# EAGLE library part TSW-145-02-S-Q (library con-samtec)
THROUGH-HOLE .025" SQ POST HEADER Source: Samtec TSW.pdf
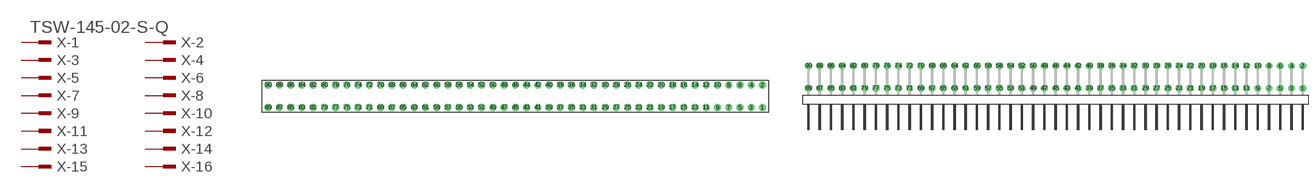
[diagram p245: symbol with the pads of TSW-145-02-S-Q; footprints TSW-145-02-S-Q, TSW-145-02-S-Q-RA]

Designator prefix X; gates -1=MPINV -2=MPIN -3=MPIN -4=MPIN -5=MPIN -6=MPIN -7=MPIN -8=MPIN -9=MPIN -10=MPIN -11=MPIN -12=MPIN -13=MPIN -14=MPIN -15=MPIN -16=MPIN -17=MPIN -18=MPIN -19=MPIN -20=MPIN -21=MPIN -22=MPIN -23=MPIN -24=MPIN -25=MPIN -26=MPIN -27=MPIN -28=MPIN -29=MPIN -30=MPIN -31=MPIN -32=MPIN -33=MPIN -34=MPIN -35=MPIN -36=MPIN -37=MPIN -38=MPIN -39=MPIN -40=MPIN -41=MPIN -42=MPIN -43=MPIN -44=MPIN -45=MPIN -46=MPIN -47=MPIN -48=MPIN -49=MPIN -50=MPIN -51=MPIN -52=MPIN -53=MPIN -54=MPIN -55=MPIN -56=MPIN -57=MPIN -58=MPIN -59=MPIN -60=MPIN -61=MPIN -62=MPIN -63=MPIN -64=MPIN -65=MPIN -66=MPIN -67=MPIN -68=MPIN -69=MPIN -70=MPIN -71=MPIN -72=MPIN -73=MPIN -74=MPIN -75=MPIN -76=MPIN -77=MPIN -78=MPIN -79=MPIN -80=MPIN -81=MPIN -82=MPIN -83=MPIN -84=MPIN -85=MPIN -86=MPIN -87=MPIN -88=MPIN -89=MPIN -90=MPIN

## TSW-145-02-S-Q (OC_FARNELL: unknown; OC_NEWARK: unknown)  [TSW-145-02-S-Q]
1  -1:1  pas
2  -2:1  pas
3  -3:1  pas
4  -4:1  pas
5  -5:1  pas
6  -6:1  pas
7  -7:1  pas
8  -8:1  pas
9  -9:1  pas
10  -10:1  pas
11  -11:1  pas
12  -12:1  pas
13  -13:1  pas
14  -14:1  pas
15  -15:1  pas
16  -16:1  pas
17  -17:1  pas
18  -18:1  pas
19  -19:1  pas
20  -20:1  pas
21  -21:1  pas
22  -22:1  pas
23  -23:1  pas
24  -24:1  pas
25  -25:1  pas
26  -26:1  pas
27  -27:1  pas
28  -28:1  pas
29  -29:1  pas
30  -30:1  pas
31  -31:1  pas
32  -32:1  pas
33  -33:1  pas
34  -34:1  pas
35  -35:1  pas
36  -36:1  pas
37  -37:1  pas
38  -38:1  pas
39  -39:1  pas
40  -40:1  pas
41  -41:1  pas
42  -42:1  pas
43  -43:1  pas
44  -44:1  pas
45  -45:1  pas
46  -46:1  pas
47  -47:1  pas
48  -48:1  pas
49  -49:1  pas
50  -50:1  pas
51  -51:1  pas
52  -52:1  pas
53  -53:1  pas
54  -54:1  pas
55  -55:1  pas
56  -56:1  pas
57  -57:1  pas
58  -58:1  pas
59  -59:1  pas
60  -60:1  pas
61  -61:1  pas
62  -62:1  pas
63  -63:1  pas
64  -64:1  pas
65  -65:1  pas
66  -66:1  pas
67  -67:1  pas
68  -68:1  pas
69  -69:1  pas
70  -70:1  pas
71  -71:1  pas
72  -72:1  pas
73  -73:1  pas
74  -74:1  pas
75  -75:1  pas
76  -76:1  pas
77  -77:1  pas
78  -78:1  pas
79  -79:1  pas
80  -80:1  pas
81  -81:1  pas
82  -82:1  pas
83  -83:1  pas
84  -84:1  pas
85  -85:1  pas
86  -86:1  pas
87  -87:1  pas
88  -88:1  pas
89  -89:1  pas
90  -90:1  pas

## TSW-145-02-S-Q-RA (OC_FARNELL: unknown; OC_NEWARK: unknown)  [TSW-145-02-S-Q-RA]
Pads as for TSW-145-02-S-Q

## Footprint TSW-145-02-S-Q (pad centres in mm)
THROUGH-HOLE .025" SQ POST HEADER Source: Samtec TSW.pdf
drill 1 pad 1.5 octagon: 1 55.88,-2.54; 2 55.88,2.54; 3 53.34,-2.54; 4 53.34,2.54; 5 50.8,-2.54; 6 50.8,2.54; 7 48.26,-2.54; 8 48.26,2.54; 9 45.72,-2.54; 10 45.72,2.54; 11 43.18,-2.54; 12 43.18,2.54; 13 40.64,-2.54; 14 40.64,2.54; 15 38.1,-2.54; 16 38.1,2.54; 17 35.56,-2.54; 18 35.56,2.54; 19 33.02,-2.54; 20 33.02,2.54; 21 30.48,-2.54; 22 30.48,2.54; 23 27.94,-2.54; 24 27.94,2.54; 25 25.4,-2.54; 26 25.4,2.54; 27 22.86,-2.54; 28 22.86,2.54; 29 20.32,-2.54; 30 20.32,2.54; 31 17.78,-2.54; 32 17.78,2.54; 33 15.24,-2.54; 34 15.24,2.54; 35 12.7,-2.54; 36 12.7,2.54; 37 10.16,-2.54; 38 10.16,2.54; 39 7.62,-2.54; 40 7.62,2.54; 41 5.08,-2.54; 42 5.08,2.54; 43 2.54,-2.54; 44 2.54,2.54; 45 0,-2.54; 46 0,2.54; 47 -2.54,-2.54; 48 -2.54,2.54; 49 -5.08,-2.54; 50 -5.08,2.54; 51 -7.62,-2.54; 52 -7.62,2.54; 53 -10.16,-2.54; 54 -10.16,2.54; 55 -12.7,-2.54; 56 -12.7,2.54; 57 -15.24,-2.54; 58 -15.24,2.54; 59 -17.78,-2.54; 60 -17.78,2.54; 61 -20.32,-2.54; 62 -20.32,2.54; 63 -22.86,-2.54; 64 -22.86,2.54; 65 -25.4,-2.54; 66 -25.4,2.54; 67 -27.94,-2.54; 68 -27.94,2.54; 69 -30.48,-2.54; 70 -30.48,2.54; 71 -33.02,-2.54; 72 -33.02,2.54; 73 -35.56,-2.54; 74 -35.56,2.54; 75 -38.1,-2.54; 76 -38.1,2.54; 77 -40.64,-2.54; 78 -40.64,2.54; 79 -43.18,-2.54; 80 -43.18,2.54; 81 -45.72,-2.54; 82 -45.72,2.54; 83 -48.26,-2.54; 84 -48.26,2.54; 85 -50.8,-2.54; 86 -50.8,2.54; 87 -53.34,-2.54; 88 -53.34,2.54; 89 -55.88,-2.54; 90 -55.88,2.54

## Footprint TSW-145-02-S-Q-RA (pad centres in mm)
THROUGH-HOLE .025" SQ POST HEADER Source: Samtec TSW.pdf
drill 1 pad 1.5 octagon: 1 55.88,1.524; 2 55.88,6.604; 3 53.34,1.524; 4 53.34,6.604; 5 50.8,1.524; 6 50.8,6.604; 7 48.26,1.524; 8 48.26,6.604; 9 45.72,1.524; 10 45.72,6.604; 11 43.18,1.524; 12 43.18,6.604; 13 40.64,1.524; 14 40.64,6.604; 15 38.1,1.524; 16 38.1,6.604; 17 35.56,1.524; 18 35.56,6.604; 19 33.02,1.524; 20 33.02,6.604; 21 30.48,1.524; 22 30.48,6.604; 23 27.94,1.524; 24 27.94,6.604; 25 25.4,1.524; 26 25.4,6.604; 27 22.86,1.524; 28 22.86,6.604; 29 20.32,1.524; 30 20.32,6.604; 31 17.78,1.524; 32 17.78,6.604; 33 15.24,1.524; 34 15.24,6.604; 35 12.7,1.524; 36 12.7,6.604; 37 10.16,1.524; 38 10.16,6.604; 39 7.62,1.524; 40 7.62,6.604; 41 5.08,1.524; 42 5.08,6.604; 43 2.54,1.524; 44 2.54,6.604; 45 0,1.524; 46 0,6.604; 47 -2.54,1.524; 48 -2.54,6.604; 49 -5.08,1.524; 50 -5.08,6.604; 51 -7.62,1.524; 52 -7.62,6.604; 53 -10.16,1.524; 54 -10.16,6.604; 55 -12.7,1.524; 56 -12.7,6.604; 57 -15.24,1.524; 58 -15.24,6.604; 59 -17.78,1.524; 60 -17.78,6.604; 61 -20.32,1.524; 62 -20.32,6.604; 63 -22.86,1.524; 64 -22.86,6.604; 65 -25.4,1.524; 66 -25.4,6.604; 67 -27.94,1.524; 68 -27.94,6.604; 69 -30.48,1.524; 70 -30.48,6.604; 71 -33.02,1.524; 72 -33.02,6.604; 73 -35.56,1.524; 74 -35.56,6.604; 75 -38.1,1.524; 76 -38.1,6.604; 77 -40.64,1.524; 78 -40.64,6.604; 79 -43.18,1.524; 80 -43.18,6.604; 81 -45.72,1.524; 82 -45.72,6.604; 83 -48.26,1.524; 84 -48.26,6.604; 85 -50.8,1.524; 86 -50.8,6.604; 87 -53.34,1.524; 88 -53.34,6.604; 89 -55.88,1.524; 90 -55.88,6.604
